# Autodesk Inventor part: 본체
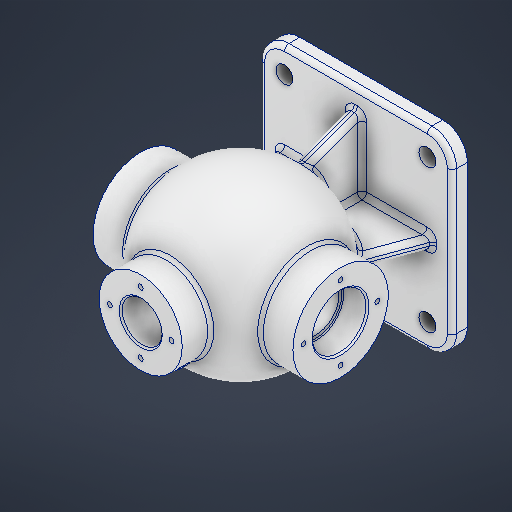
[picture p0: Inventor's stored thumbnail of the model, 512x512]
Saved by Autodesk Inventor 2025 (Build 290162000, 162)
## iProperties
Created: 2025-08
Part Number: 본체
Material: 알루미늄 6061
Document SubType Name: Modeling
Designer: infra027
Density: 2.7 g/cm^3
Appearance: 알루미늄 - 평지
Mass: 1526.73 g
Surface Area: 1173.98 cm^2
Volume: 565.456 cm^3
Author: infra027
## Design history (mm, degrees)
sketch "스케치1"
  geometry: L1 (-62.5, -62.5)-(62.5, -62.5); L2 (62.5, -62.5)-(62.5, 62.5); L3 (62.5, 62.5)-(-62.5, 62.5); L4 (-62.5, 62.5)-(-62.5, -62.5); L5 (-62.5, -62.5)-(62.5, 62.5); L6 (62.5, -62.5)-(-62.5, 62.5); 1 further point
  constraints: 12 end point, 2 midpoint, 2 parallel, 1 horizontal, 1 perpendicular
  dimensions: "d0" = 125 distance of L3.end L2.end; "d1" = 125 distance of L2.end L1.end
extrude "돌출1" new body sketch "스케치1" stored distance "d2" = 10; taper "d3" = 0 deg
sketch "스케치2"
  geometry: L1 (-62.5, -5)-(62.5, -5) reference; L2 (54, 80)-(-54, 80); L3 (54, 80)-(162, 80); C1 r 54 at (0, 80); 4 further points
  constraints: 4 end point, 2 horizontal, 1 centre point, 1 coincident, 1 collinear, 1 midpoint
  dimensions: "d4" = 108 diameter of C1; "d5" = 0 horizontal distance of point (0, 0) C1.centre; "d6" = 85 distance from line of L1 C1.centre; "d7" = 108 distance of L2.start L2.end; "d8" = 180 deg angle of L2 L3 (derived)
revolve "회전1" sketch "스케치2" stored, may be unused: angle "d9" = 360 deg
sketch "스케치4"
  geometry: L1 (62.5, 5)-(130.065, 5); L2 (-62.5, 5)-(62.5, 5) reference; L3 (50.5, 5)-(31.217, 57.979); L4 (31.217, 57.979)-(-31.217, 57.979); L5 (-31.217, 57.979)-(-50.5, 5); L6 (62.5, -5)-(62.5, 5) reference; L7 (-62.5, -5)-(-62.5, 5) reference; 1 further point
  constraints: 8 end point, 2 point on line, 1 horizontal, 1 parallel
  dimensions: "d16" = 12 distance of L3.start L1.start; "d17" = 12 distance of L2.start L5.end; "d18" = 20 deg angle of L6 L3; "d19" = 20 deg angle of L7 L5; "d20" = 62.43455 distance of L3.end L4.end
extrude "돌출2" join sketch "스케치4" stored distance "d21" = 8; taper "d22" = 0 deg
sketch "스케치5"
  geometry: L1 (-62.5, 5)-(62.5, 5) reference; L2 (50.5, 5)-(28.797, 64.628); L3 (28.797, 64.628)-(-28.797, 64.628); L4 (4, 41.186)-(4, 5) reference; L5 (-28.797, 64.628)-(-50.5, 5); L6 (62.5, -5)-(62.5, 5) reference; L7 (-62.5, 5)-(-62.5, -5) reference; 3 further points
  constraints: 6 end point, 1 midpoint, 1 perpendicular, 1 point on line, 1 vertical alignment
  dimensions: "d23" = 12 distance of L1.end L2.start; "d24" = 12 distance of L1.start L5.end; "d25" = 20 deg angle of L6 L2; "d26" = 20 deg angle of L5 L7; "d27" = 57.59438 distance of L2.end L3.end
extrude "돌출3" join sketch "스케치5" stored distance "d28" = 8; taper "d29" = 0 deg
sketch "스케치6"
  geometry: L1 (-65, 111)-(65, 111); L2 (65, 111)-(65, 80); L3 (65, 80)-(-65, 80); L4 (-65, 80)-(-65, 111); L5 (62.5, -5)-(-62.5, -5) reference; L6 (-62.5, 5)-(62.5, 5) reference; 3 further points
  constraints: 8 end point, 2 midpoint, 2 parallel, 1 horizontal, 1 perpendicular, 1 vertical alignment
  dimensions: "d30" = 130 distance of L2.end L3.end; "d31" = 31 distance of L1.end L2.end; "d32" = 85 distance between parallel lines of L3 L5
revolve "회전2" sketch "스케치6" stored, may be unused: angle "d33" = 90 deg
sketch "스케치7"
  geometry: L1 (0, 145)-(27, 145); L2 (27, 145)-(27, 80); L3 (27, 80)-(0, 80); L4 (0, 80)-(0, 145); L5 (-62.5, 5)-(62.5, 5) reference; L6 (62.5, -5)-(-62.5, -5) reference; 2 further points
  constraints: 8 end point, 2 parallel, 1 horizontal, 1 midpoint, 1 perpendicular, 1 point on line
  dimensions: "d34" = 27 distance of L2.end L3.end; "d35" = 65 distance of L1.end L2.end; "d36" = 150 distance between parallel lines of L6 L1
revolve "회전3" sketch "스케치7" stored, may be unused: angle "d37" = 90 deg
sketch "스케치8"
  geometry: L1 (-44, 80)-(44, 80); L2 (-44, 80)-(44, 80); L3 (-62.5, 5)-(62.5, 5) reference; L4 (62.5, -5)-(-62.5, -5) reference; C1 r 44 at (0, 80); 6 further points
  constraints: 4 end point, 3 midpoint, 2 horizontal, 1 centre point, 1 coincident, 1 collinear, 1 vertical alignment
  dimensions: "d38" = 88 diameter of C1; "d39" = 88 distance of L1.start L1.end; "d40" = 0 distance between parallel lines of L1 L2 (derived); "d41" = 85 distance from line of L4 C1.centre
revolve "회전4" sketch "스케치8" stored, may be unused: angle "d42" = 360 deg
sketch "스케치9"
  geometry: C1 r 13 at (0, 0); C2 r 27 at (0, 0) reference; 1 further point
  constraints: 1 centre point, 1 concentric
  dimensions: "d43" = 26 diameter of C1
extrude "돌출4" cut sketch "스케치9" distance "d44" = 65; taper "d45" = 0 deg
sketch "스케치10"
  geometry: C1 r 15 at (0, 0); C2 r 31 at (0, 0) reference; 1 further point
  constraints: 1 centre point, 1 concentric
  dimensions: "d46" = 30 diameter of C1
extrude "돌출5" cut sketch "스케치10" extent not by distance; stored distance "d47" = 0; taper "d48" = 0 deg
sketch "스케치11"
  geometry: C1 r 17.5 at (0, 0); C2 r 31 at (0, 0) reference; 1 further point
  constraints: 1 centre point, 1 concentric
  dimensions: "d49" = 35 diameter of C1
extrude "돌출6" cut sketch "스케치11" distance "d50" = 16; taper "d51" = 0 deg
sketch "스케치12"
  geometry: C1 r 17.5 at (0, 0); C2 r 31 at (0, 0) reference; 1 further point
  constraints: 1 centre point, 1 concentric
  dimensions: "d52" = 35 diameter of C1
extrude "돌출7" cut sketch "스케치12" distance "d53" = 16; taper "d54" = 0 deg
sketch "스케치13"
  geometry: L1 (0, 0)-(24, 0); L2 (0, 0)-(24, 0); L3 (0, 0)-(0, 24); L4 (0, 0)-(0, 24); L5 (0, 0)-(-24, 0); L6 (0, 0)-(-24, 0); L7 (0, 0)-(0, -24); L8 (0, 0)-(0, -24); C1 r 24 at (0, 0); C2 r 31 at (0, 0) reference; C3 r 15 at (0, 0) reference; C4 r 24 at (0, 0); C5 r 24 at (0, 0); C6 r 24 at (0, 0); 11 further points
  constraints: 16 end point, 6 coincident, 4 centre point, 2 horizontal, 1 collinear, 1 concentric, 39 other
  dimensions: "d62" = 48 diameter of C1; "d63" = 24 distance of L1.start L1.end; "d64" = 0 distance between parallel lines of L1 L2 (derived); "d67" = 360 deg dimension on C1.centre point (-80, 0) (derived)
hole "구멍1" sketch "스케치13" at (24, 0), (0, 24), (-24, 0), (0, -24) diameter "d55" = 3.242; stored, may be unused: countersink angle "d59" = 90 deg, drill point angle "d61" = 118 deg; dims "d56" = 12, "d57" = 4, "d58" = 2, "d60" = 15
sketch "스케치14"
  geometry: L1 (0, 0)-(0, 20); L2 (0, 0)-(20, 0); L3 (0, 0)-(-20, 0); L4 (0, 0)-(0, 20); L5 (0, 0)-(0, -20); L6 (0, 0)-(-20, 0); L7 (0, 0)-(20, 0); L8 (0, 0)-(0, -20); C1 r 20 at (0, 0); C2 r 20 at (0, 0); C3 r 20 at (0, 0); C4 r 20 at (0, 0); 8 further points
  constraints: 16 end point, 10 coincident, 4 centre point, 1 horizontal, 1 perpendicular, 1 vertical, 31 other
  dimensions: "d76" = 40 diameter of C1; "d77" = 20 distance of L1.start L1.end; "d78" = 90 deg angle of L2 L1 (derived); "d81" = 360 deg dimension on point (0, 0) L1.end (derived)
hole "구멍2" sketch "스케치14" at (0, 20), (-20, 0), (0, -20), (20, 0) diameter "d69" = 3.242; stored, may be unused: countersink angle "d73" = 90 deg, drill point angle "d75" = 118 deg; dims "d70" = 9, "d71" = 4, "d72" = 2, "d74" = 11
chamfer "모따기1" distance "d83" = 1; stored, may be unused: second distance "d84" = 2, angle "d85" = 45 deg
chamfer "모따기2" distance "d86" = 1; stored, may be unused: second distance "d87" = 2, angle "d88" = 45 deg
chamfer "모따기3" distance "d89" = 1; stored, may be unused: second distance "d90" = 2, angle "d91" = 45 deg
fillet "모깎기1" dims "d92" = 3
fillet "모깎기2" dims "d93" = 16
fillet "모깎기3" dims "d94" = 3
fillet "모깎기4" dims "d95" = 3
fillet "모깎기5" dims "d96" = 3
fillet "모깎기6" dims "d97" = 3
sketch "스케치15"
  geometry: L1 (46.5, 46.5)-(-46.5, 46.5); L2 (-46.5, 46.5)-(-46.5, -46.5); L3 (-46.5, -46.5)-(46.5, -46.5); L4 (46.5, -46.5)-(46.5, 46.5); L5 (46.5, 46.5)-(-46.5, -46.5); L6 (-46.5, 46.5)-(46.5, -46.5); 5 further points
  constraints: 12 end point, 4 coincident, 2 midpoint, 2 parallel, 1 horizontal, 1 perpendicular
  dimensions: "d105" = 93 distance of L3.end L2.end; "d106" = 93 distance of L2.end L1.end
hole "구멍3" sketch "스케치15" at (-46.5, -46.5), (46.5, -46.5), (46.5, 46.5), (-46.5, 46.5) diameter "d98" = 11; stored, may be unused: countersink angle "d102" = 90 deg, drill point angle "d104" = 118 deg; dims "d99" = 9, "d100" = 4, "d101" = 2, "d103" = 11
fillet "모깎기7" dims "d113" = 0.6
node "작업 평면1"
sketch "스케치16" dims "d0" = 125, "d1" = 125
  geometry: L1 (18.056, 147.004)-(74.944, 147.004); L2 (74.944, 147.004)-(74.944, 134.996); L3 (74.944, 134.996)-(18.056, 134.996); L4 (18.056, 134.996)-(18.056, 147.004); L5 (73.5, 150)-(19.5, 150) reference; L6 (0, 0)-(93, 0) reference; 4 further points
  constraints: 3 midpoint, 1 vertical alignment, 2 other
  dimensions: "d116" = 134.99593 distance between parallel lines of L3 L6; "d117" = 56.88885 distance between parallel lines of L2 L4; "d124" = 9 distance from line of L5 point (74.944, 141)
feature "엠보싱3" sketch "스케치16" dims "d0" = 125, "d1" = 125, "d122" = 0.5, "d123" = 0
feature "Җ耀Ҙ耀Қ耀Ҝ耀Ҟ耀Ҡ耀Ң耀Ҥ耀" dims "d0" = 125, "d1" = 125, "d2" = 10, "d3" = 0, "d4" = 108, "d5" = 0, "d6" = 85, "d7" = 108, "d8" = 180 deg (derived), "d9" = 360 deg, "d16" = 12, "d17" = 12, "d18" = 20 deg, "d19" = 20 deg, "d20" = 62.43455, "d21" = 8, "d22" = 0, "d23" = 12, "d24" = 12, "d25" = 20 deg, "d26" = 20 deg, "d27" = 57.59438, "d28" = 8, "d29" = 0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
node "솔리드1"
mirror "미러1"
node "스케치 - 원형 패턴1" dims "d67" = 360 deg (derived)
node "스케치 - 원형 패턴2" dims "d81" = 360 deg (derived)
feature "A9D066F2-1C7D-4E18-AEED-F7BC21143FA4" dims "d98" = 11, "d99" = 9, "d100" = 4, "d101" = 2, "d102" = 90 deg, "d103" = 11, "d104" = 118 deg
